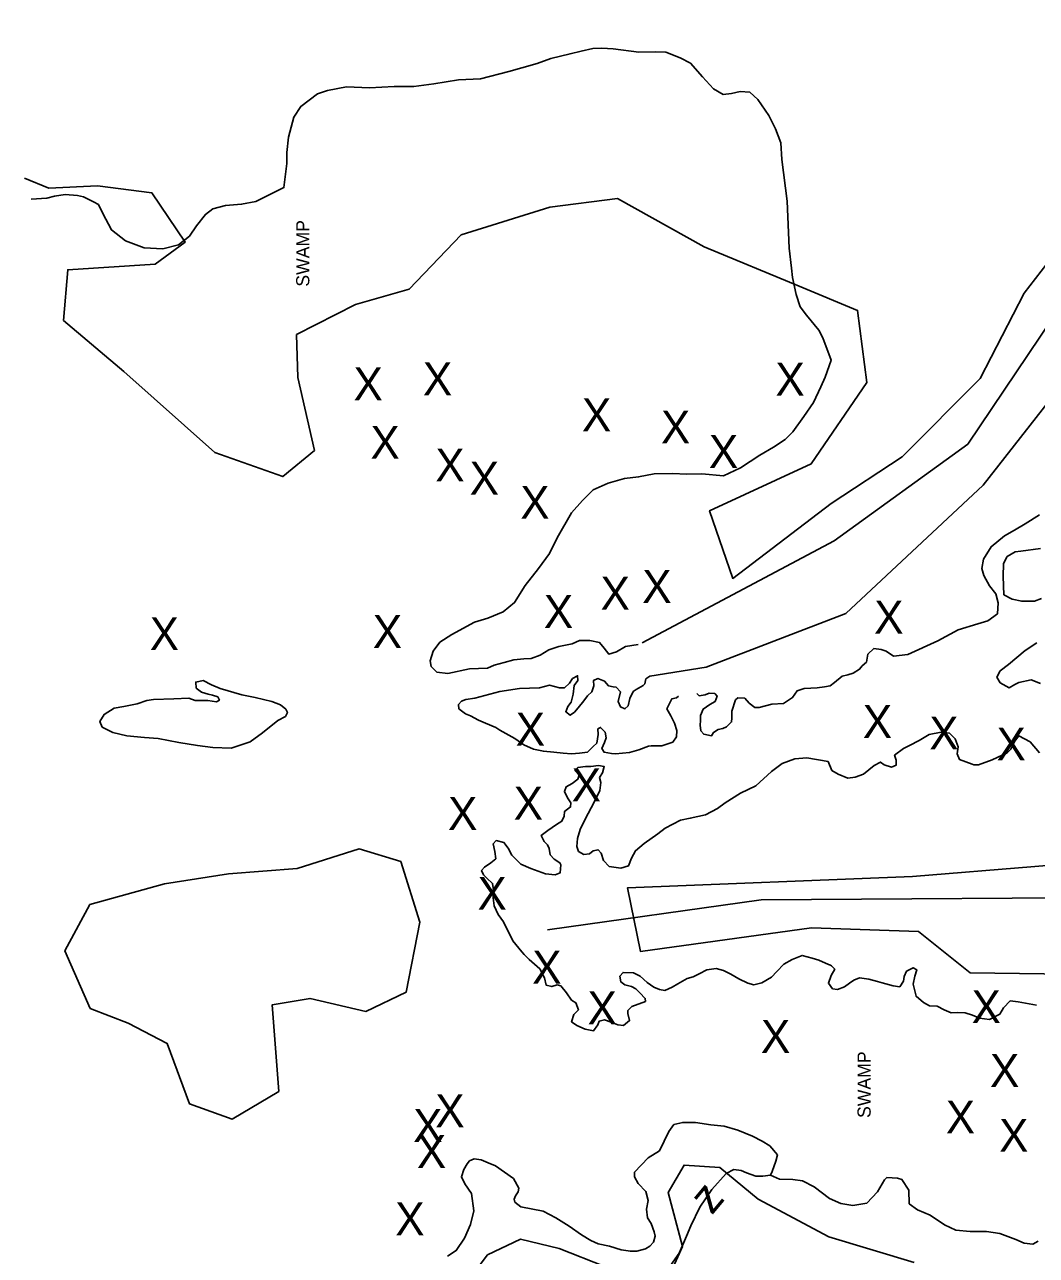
# Model space of a CAD drawing. Extents: x 2030130 to 2036320, y 723205 to 762423.
# Drawn here: x 2033457.3 to 2033764.6, y 737672 to 738045.8 of the extents above; entities that cross this region are included whole.
import ezdxf

# ---------------------------------------------------------------- set-up
doc = ezdxf.new("R2010")
doc.units = 0
for name, color, linetype in [('Draft_Station Tics Major', 7, 'Continuous'), ('Exist Terrain Model Ground Surface', 7, 'Continuous'), ('Prop Alignment Horizontal', 7, 'Continuous'), ('Prop Alignment Vertical', 7, 'Continuous')]:
    doc.layers.add(name, color=color, linetype=linetype)

msp = doc.modelspace()

# ---------------------------------------------------------------- linework, layer by layer
at = {"layer": 'Draft_Station Tics Major'}
for points in [[(2033781.5, 737990.94), (2033760.88, 737964.24), (2033747.53, 737938.3), (2033723.82, 737914.57), (2033702.29, 737900.41), (2033672.4, 737877.61), (2033665.33, 737898.19), (2033696.22, 737912.41), (2033713.11, 737937.08), (2033710.29, 737959.02), (2033692.53, 737966.39), (2033663.66, 737978.36), (2033637.36, 737993.04), (2033616.87, 737990.33), (2033589.93, 737981.95), (2033574.15, 737965.43), (2033557.84, 737960.78), (2033539.85, 737951.68), (2033540.35, 737938.62), (2033545.4, 737916.5), (2033535.74, 737908.54), (2033515.07, 737915.85), (2033487.41, 737940.44), (2033469.17, 737956), (2033470.42, 737971.39), (2033496.95, 737973.05), (2033506.06, 737979.7), (2033495.98, 737994.69), (2033479.42, 737996.89), (2033464.64, 737996.16), (2033457.33, 737999.22)], [(2033499.82, 737784.91), (2033519.26, 737787.91), (2033540.12, 737789.56), (2033558.96, 737795.48), (2033571.53, 737791.64), (2033577.32, 737773.2), (2033573.17, 737751.94), (2033560.91, 737746.14), (2033544, 737750.07), (2033532.49, 737748.08), (2033534.55, 737721.81), (2033520.39, 737713.42), (2033507.45, 737718.05), (2033500.6, 737736.39), (2033488.74, 737742.58)], [(2033781.79, 737757.38), (2033744.5, 737757.8), (2033728.83, 737770.41), (2033696.3, 737771.51), (2033644.35, 737764.35), (2033640.42, 737783.68), (2033726.95, 737787.05), (2033801.29, 737793.2)], [(2033488.74, 737742.58), (2033477.24, 737747.05), (2033469.58, 737764.48), (2033477.14, 737778.55), (2033499.82, 737784.91)], [(2033653.8, 737667.32), (2033657.1, 737674.75), (2033652.75, 737691.1), (2033657.62, 737699.45), (2033668.41, 737698.75), (2033680.11, 737689.15), (2033701.6, 737677.71), (2033727.44, 737669.82)], [(2033593.73, 737666.73), (2033597.94, 737672.21), (2033607.93, 737676.94), (2033619.62, 737674.1), (2033633.56, 737668.67)]]:
    msp.add_lwpolyline(points, dxfattribs=at)
at = {"layer": 'Exist Terrain Model Ground Surface'}
msp.add_lwpolyline([(2033964.63, 738000.66), (2033931.26, 737901.48), (2033914.62, 737851.16), (2033850.12, 737809.52), (2033803.03, 737780.8), (2033680.98, 737780.05), (2033616.14, 737770.94)], dxfattribs=at)
at = {"layer": 'Prop Alignment Horizontal'}
msp.add_line((2033647.24, 737847.97), (2033664.33, 737850.64), dxfattribs=at)
for points in [[(2033664.33, 737850.64), (2033706.74, 737866.99), (2033748.47, 737905.92), (2033780.57, 737947.09), (2033807.33, 737978.27), (2033840.77, 738020.75), (2033893, 738032.33), (2033936.05, 738045.81)], [(2033592.41, 737850.17), (2033585.83, 737848.73), (2033582.48, 737849.2), (2033580.79, 737850.89), (2033580.5, 737852.61), (2033581.36, 737855.5), (2033583.47, 737858.23), (2033587.02, 737860.6), (2033593.91, 737864.35), (2033597.96, 737865.51), (2033602.7, 737867.46), (2033606.13, 737870.29), (2033609.35, 737875.51), (2033613.36, 737880.64), (2033616.7, 737885.19), (2033619.05, 737889.96), (2033623.44, 737897.53), (2033626.76, 737901.29), (2033629.94, 737904.53), (2033634.55, 737906.6), (2033639.53, 737907.95), (2033643.77, 737908.45), (2033648.48, 737909.34), (2033654.1, 737909.48), (2033658.46, 737909.25), (2033662.96, 737909.42), (2033669.55, 737908.81), (2033674.76, 737911.21), (2033680.59, 737915.05), (2033684.8, 737917.46), (2033688.29, 737919.83), (2033690.66, 737922.16), (2033694, 737926.78), (2033696.86, 737931.01), (2033699.08, 737935.85), (2033700.4, 737938.73), (2033702.23, 737943.91), (2033699.74, 737950.64), (2033698.53, 737952.98), (2033694.74, 737957.62), (2033692.87, 737960.11), (2033691.64, 737963.9), (2033690.49, 737969.01), (2033690.22, 737971.86), (2033689.5, 737977.95), (2033688.89, 737992.24), (2033687.25, 738004.83), (2033687.03, 738009.92), (2033685.34, 738014.19), (2033683.38, 738018.2), (2033679.98, 738023.03), (2033677.52, 738025.33), (2033674.68, 738025.52), (2033672.03, 738024.92), (2033669.51, 738024.58), (2033666.51, 738026.3), (2033663.22, 738030), (2033659.54, 738034.12), (2033656.41, 738035.77), (2033652.08, 738037.45), (2033648.84, 738037.52), (2033643.82, 738037.43), (2033636.05, 738038.46), (2033632.61, 738038.67), (2033629.84, 738038.53), (2033626.38, 738037.75), (2033623, 738036.96), (2033617.15, 738035.57), (2033612.95, 738034.01), (2033608.36, 738032.66), (2033604.38, 738031.56), (2033595.74, 738029.37), (2033589.12, 738029.05), (2033581.56, 738027.83), (2033575.53, 738027.04), (2033569.52, 738027.03), (2033562.04, 738026.6), (2033555.05, 738026.89), (2033549.34, 738025.82), (2033546.28, 738024.77), (2033541.17, 738020.98), (2033539.05, 738017.66), (2033537.46, 738011.61), (2033536.97, 738007), (2033536.96, 738003.63), (2033536.07, 737996.31), (2033527.59, 737992.07), (2033523.21, 737991.24), (2033518.31, 737990.89), (2033514.52, 737989.91), (2033512.24, 737988.18), (2033509.52, 737984.74), (2033507.4, 737981.61), (2033504.04, 737978.91), (2033499.26, 737977.76), (2033493.65, 737978.01), (2033488.01, 737980.19), (2033483.72, 737983.45), (2033481.06, 737988.47), (2033479.73, 737991.14), (2033478.23, 737991.96)], [(2033821.06, 738029.09), (2033808.81, 737994.65), (2033773.1, 737961.98), (2033743.74, 737918.37), (2033703.21, 737889.06), (2033644.85, 737858.08)], [(2033478.23, 737991.96), (2033475.22, 737993.48), (2033473.38, 737993.92), (2033469.68, 737994.2), (2033466.43, 737993.68), (2033464.04, 737993.13), (2033459.28, 737992.78)], [(2033721.22, 737854.01), (2033725.52, 737854.51), (2033734.64, 737858.66), (2033740.85, 737861.96), (2033746.76, 737863.81), (2033749.88, 737864.73), (2033752.76, 737866.91), (2033752.97, 737870.2), (2033752.24, 737872.98), (2033750.31, 737875.4), (2033748.66, 737878.54), (2033748.05, 737880.66), (2033748.51, 737883.49), (2033750.9, 737887.26), (2033754.93, 737890.53), (2033757.94, 737892.31), (2033761.21, 737894.22), (2033765.49, 737896.9)], [(2033765.86, 737886.73), (2033759.84, 737885.88), (2033758.12, 737885.65), (2033755.71, 737884.25), (2033754.61, 737882.17), (2033754.46, 737878.21), (2033754.67, 737872.67), (2033757.28, 737871.36), (2033760.17, 737870.7), (2033763.99, 737870.68), (2033766.19, 737871.56)], [(2033643.66, 737857.52), (2033639.84, 737856.92), (2033637.04, 737855.33), (2033634.78, 737854.59), (2033633.3, 737856.4), (2033631.95, 737858.14), (2033629, 737858.74), (2033625.83, 737858.8), (2033623.64, 737857.8), (2033619.53, 737856.96), (2033616.54, 737855.91), (2033613.93, 737854.32), (2033611.2, 737853.26), (2033608.9, 737853.24), (2033605.85, 737852.85), (2033603, 737852.12), (2033599.95, 737851.26), (2033597.95, 737850.38), (2033592.41, 737850.17)], [(2033661.52, 737842.65), (2033662.2, 737841.98), (2033663.99, 737842.27), (2033665.25, 737842.77), (2033666.9, 737842.67), (2033667.6, 737841.86), (2033667.04, 737840.29), (2033665.37, 737839.34), (2033663.36, 737837.93), (2033662.6, 737836.04), (2033662.56, 737834.46), (2033662.47, 737833.07), (2033662.69, 737831.29), (2033663.59, 737830.28), (2033665.89, 737829.77), (2033666.51, 737830.88), (2033667.91, 737831.7), (2033669.37, 737832.07), (2033670.5, 737832.57), (2033672.05, 737834.05), (2033672.14, 737835.17), (2033672.06, 737837.35), (2033673.25, 737840.75), (2033673.92, 737841.33), (2033676.03, 737841.22), (2033677.38, 737839.74), (2033679.07, 737838.38), (2033680.39, 737838.42), (2033684.23, 737839.39), (2033687.8, 737839.64), (2033690.54, 737841.43), (2033691.91, 737843.44), (2033694.03, 737844.19), (2033696.08, 737844.34), (2033697.99, 737844.36), (2033700.24, 737844.71), (2033701.97, 737845), (2033703.31, 737846.03), (2033705.59, 737847.89), (2033707.31, 737848.32), (2033708.91, 737848.87), (2033710.91, 737850.02), (2033711.73, 737851.05), (2033713, 737852.21), (2033713.45, 737854.58), (2033715.2, 737856.32), (2033717.44, 737856.07), (2033719.01, 737855.58), (2033721.22, 737854.01)], [(2033764.77, 737858.07), (2033761.16, 737855.78), (2033758.67, 737853.59), (2033756.12, 737851.47), (2033753.57, 737849.54), (2033752.54, 737847.59), (2033753.62, 737845.92), (2033756.29, 737844.41), (2033758.09, 737845.36), (2033759.23, 737845.99), (2033763.01, 737846.83), (2033765.82, 737845.72)], [(2033594.06, 737841.3), (2033601.69, 737843.31), (2033607.64, 737844.17), (2033613.71, 737844.36), (2033616.77, 737845.22), (2033619.72, 737844.36), (2033621.3, 737844.4), (2033622.78, 737845.81), (2033623.73, 737847.18), (2033625.27, 737848.07), (2033625.3, 737846.62), (2033624.21, 737845.06), (2033623.96, 737842.43), (2033623.31, 737840.07), (2033622.3, 737838.77), (2033621.67, 737837.13), (2033623.03, 737836.05), (2033624.3, 737837.01), (2033625.45, 737838.3), (2033627.15, 737840.44), (2033628.23, 737841.94), (2033629.58, 737843.16), (2033630.15, 737844.99), (2033630.12, 737846.64), (2033631.38, 737847.21), (2033633.48, 737846.44), (2033634.63, 737845.03), (2033636.08, 737844.67), (2033637, 737844.58), (2033638.29, 737843.23), (2033637.63, 737840.21), (2033638.32, 737838.62), (2033639.62, 737837.99), (2033640.63, 737838.96), (2033641.14, 737841.19), (2033642.11, 737843.28), (2033643.05, 737843.92), (2033645.19, 737845.06), (2033645.66, 737845.64), (2033645.96, 737847.09), (2033647.24, 737847.97)], [(2033527.32, 737841.44), (2033523.25, 737842.32), (2033516.75, 737844.18), (2033514.06, 737845.3), (2033511.51, 737846.61), (2033509.32, 737846.13), (2033509.42, 737844.34), (2033511.04, 737843.05), (2033513.07, 737842.48), (2033514.39, 737842.12), (2033515.96, 737841.69), (2033516.47, 737840.69), (2033515.6, 737840.11), (2033512.97, 737840.5), (2033509.13, 737840.58), (2033507.17, 737841.29), (2033502.65, 737841.06)], [(2033502.65, 737841.06), (2033496.51, 737840.86), (2033494.46, 737840.58), (2033491.47, 737839.52), (2033487.43, 737838.69), (2033484.52, 737838.22), (2033481.51, 737836.31), (2033480.21, 737834.16), (2033480.9, 737832.5), (2033484.1, 737830.85), (2033488.36, 737829.83), (2033493.76, 737829.32), (2033497.84, 737828.96), (2033504.21, 737827.77), (2033509.79, 737826.86), (2033514.46, 737826.29), (2033520.06, 737826.1), (2033525.84, 737828.02), (2033529.53, 737830.71), (2033534.23, 737834.43), (2033536.56, 737835.7), (2033537.12, 737836.94), (2033536.61, 737837.87), (2033534.99, 737839.23), (2033532.44, 737840.27), (2033527.32, 737841.44)], [(2033594.06, 737841.3), (2033591.35, 737840.83), (2033590.02, 737840.33), (2033589.14, 737839.36), (2033589.24, 737838.04), (2033591.25, 737836.48), (2033592.69, 737835.86), (2033595.17, 737834.61), (2033597.32, 737833.64), (2033600.46, 737832.32), (2033601.63, 737831.57), (2033606.25, 737828.96), (2033608.98, 737827.06), (2033611.92, 737825.74), (2033614.88, 737825.15), (2033618.03, 737824.81), (2033620.86, 737824.56), (2033623.37, 737824.37), (2033625.88, 737824.58), (2033628.26, 737824.85), (2033629.94, 737826.53), (2033631.09, 737827.63), (2033631.54, 737830.26), (2033631.44, 737831.91), (2033632.25, 737832.35), (2033633.6, 737830.94), (2033633.89, 737829.22), (2033633.4, 737827.84), (2033632.63, 737825.95), (2033633.33, 737824.81), (2033635.57, 737824.43), (2033636.82, 737824.34), (2033640.98, 737824.77), (2033643.9, 737825.57), (2033646.83, 737826.69), (2033647.62, 737826.8), (2033650.85, 737826.8), (2033654.17, 737827.91), (2033655.27, 737829.54), (2033655.44, 737831.45), (2033654.7, 737833.64), (2033653.62, 737835.91), (2033652.35, 737837.98), (2033653.87, 737841.04), (2033655.26, 737841.34), (2033655.89, 737841.91)], [(2033765.49, 737824.62), (2033762.66, 737828.04), (2033759.27, 737829.83), (2033758.05, 737828.15), (2033756.87, 737825.73), (2033755.73, 737824.7), (2033751.2, 737822.56), (2033747.01, 737821), (2033745.56, 737820.97), (2033745.04, 737821.24), (2033741.24, 737822.58), (2033740.49, 737824.31), (2033740.86, 737826.48), (2033739.93, 737828.87), (2033738.19, 737830.62), (2033735.69, 737830.94), (2033732.04, 737830.23), (2033729.04, 737828.45), (2033726.1, 737826.87), (2033724.23, 737825.98), (2033721.55, 737823.93), (2033722.05, 737822.41), (2033722.01, 737820.95), (2033720.55, 737820.33), (2033718.39, 737821.03), (2033717.22, 737821.85), (2033715.35, 737820.77), (2033712.06, 737818.14), (2033709.6, 737817.27), (2033707.29, 737816.99), (2033704.35, 737818.18), (2033702.52, 737819.34), (2033701.33, 737822.07)], [(2033701.33, 737822.07), (2033694.89, 737823.13), (2033691.26, 737822.82), (2033687.4, 737821.38), (2033684.18, 737818.95), (2033679.34, 737814.64), (2033674.74, 737812.43), (2033670.06, 737809.43), (2033667.71, 737807.7), (2033664.11, 737805.8), (2033659.47, 737804.78), (2033656.49, 737804.19), (2033651.89, 737801.78), (2033649.67, 737800.05), (2033645.52, 737797.17), (2033642.83, 737794.93), (2033641.67, 737792.71), (2033640.76, 737790.35), (2033638.37, 737789.62), (2033634.88, 737790.09), (2033633.14, 737791.97), (2033632.46, 737794.16), (2033631.5, 737795.24), (2033629.98, 737794.94), (2033628.83, 737793.98), (2033627.11, 737793.75), (2033625.55, 737794.71), (2033625.06, 737796.24), (2033625.24, 737798.61), (2033626.09, 737801.42), (2033627.55, 737804.56), (2033630.3, 737809.71), (2033632.02, 737813.23), (2033632.27, 737815.6), (2033631.91, 737817.19), (2033632.8, 737818.56), (2033633.37, 737820.46), (2033631.6, 737820.82), (2033629.28, 737820.48), (2033627.63, 737820.52), (2033625.38, 737820.17), (2033624.44, 737819.33), (2033625.73, 737817.92), (2033625.31, 737816.61), (2033623.63, 737815.33), (2033621.83, 737814.38), (2033621.27, 737812.94), (2033622.15, 737811.01), (2033623.24, 737809.47), (2033623.14, 737808.22), (2033621.33, 737806.87), (2033621.17, 737805.42), (2033620.48, 737803.86), (2033618.87, 737802.84), (2033616.26, 737801.11), (2033614.18, 737799.51), (2033615.13, 737797.71), (2033616.1, 737796.76), (2033616.6, 737795.57), (2033616.96, 737793.71), (2033618.11, 737792.37), (2033619.87, 737791.27), (2033620.19, 737790.67), (2033619.94, 737788.17), (2033618.47, 737787.61), (2033615.51, 737787.87), (2033611.06, 737789.49), (2033607.99, 737790.87), (2033605.28, 737793.57), (2033604.14, 737795.71), (2033602.86, 737797.45), (2033600.5, 737798.03), (2033599.62, 737796.99), (2033600.1, 737794.67), (2033600.38, 737792.49), (2033598.96, 737791.2), (2033596.96, 737789.93), (2033596.08, 737788.89), (2033596.64, 737787.63), (2033597.68, 737786.62), (2033599.42, 737784.99), (2033599.71, 737783.01), (2033599.66, 737780.64), (2033599.93, 737778.19), (2033601.13, 737775.53), (2033602.73, 737773.32), (2033605.57, 737767.58), (2033608.33, 737764.22)], [(2033608.33, 737764.22), (2033609.04, 737763.42), (2033610.52, 737761.87), (2033613.76, 737759.03), (2033615.21, 737756.29), (2033615.69, 737754.1), (2033617.4, 737753.67), (2033619.06, 737754.23), (2033620.17, 737753.87), (2033621.91, 737751.79), (2033623.38, 737749.58), (2033624.68, 737748.76), (2033625.49, 737746.64), (2033624.07, 737745.15), (2033623.43, 737742.99), (2033624.99, 737741.83), (2033627.6, 737740.72), (2033630.1, 737740.27), (2033631.39, 737742.09), (2033631.81, 737743.13), (2033633.4, 737743.56), (2033635.5, 737742.86), (2033637.52, 737742.02), (2033639.23, 737741.85), (2033641.05, 737743.33), (2033640.5, 737745.52), (2033640.52, 737746.37), (2033641.73, 737747.6), (2033645.86, 737749.16), (2033645.81, 737750.08), (2033644.2, 737751.77), (2033642.91, 737752.98), (2033641.67, 737753.67), (2033639.57, 737754.24), (2033638.4, 737755.06), (2033638.11, 737756.78), (2033639.06, 737757.95), (2033642.22, 737757.88), (2033644.31, 737756.78), (2033646.38, 737754.95), (2033648.46, 737753.52), (2033650.15, 737752.76), (2033651.8, 737752.52), (2033654, 737753.53), (2033655.67, 737754.48), (2033658.54, 737756.13), (2033660.33, 737756.62), (2033662.2, 737757.5), (2033664.46, 737758.71), (2033667.38, 737759.17), (2033669.54, 737758.53), (2033671.82, 737757.43), (2033674.23, 737755.99), (2033676.97, 737754.68), (2033678.81, 737754.24), (2033681.26, 737754.84), (2033684.14, 737756.56), (2033685.75, 737758.24), (2033687.85, 737760.44), (2033690.39, 737761.9), (2033693.45, 737763.15), (2033696.53, 737762.29), (2033698.56, 737761.65), (2033701.5, 737760.4), (2033702.09, 737760.19), (2033702.41, 737759.99), (2033703.38, 737758.98), (2033702.28, 737757.02), (2033701.44, 737754.67), (2033702.72, 737752.99), (2033704.23, 737752.76), (2033706.36, 737753.64), (2033707.84, 737754.72), (2033709.17, 737755.62), (2033710.84, 737756.31), (2033713.73, 737755.91), (2033716.35, 737755.26), (2033717.73, 737754.77), (2033721.07, 737753.91), (2033723.11, 737753.6), (2033724.27, 737755.35), (2033724.43, 737756.74), (2033725.13, 737758.3), (2033727.13, 737759.38), (2033728.24, 737758.76), (2033727.67, 737756.86), (2033727.15, 737754.37), (2033728.06, 737750.72), (2033730.26, 737748.83), (2033732.09, 737747.86), (2033734.46, 737747.68), (2033736.61, 737746.58), (2033738.7, 737745.74), (2033740.68, 737745.76), (2033742.92, 737745.71), (2033745.21, 737744.94), (2033747.3, 737744.03), (2033750.33, 737743.7), (2033753.46, 737745.28), (2033754.63, 737747.24), (2033756.59, 737749.37)], [(2033756.59, 737749.37), (2033759.02, 737749.05), (2033764.67, 737748.01)], [(2033765.17, 737676.37), (2033763.51, 737675.44), (2033760.9, 737675.77), (2033758.31, 737676.9), (2033753.44, 737678.68), (2033749.46, 737679.32), (2033744.48, 737679.33), (2033740.16, 737679.65), (2033736.67, 737681.33), (2033732.36, 737684.2), (2033728.47, 737685.89), (2033725.97, 737687.73), (2033725.83, 737691.8), (2033723.76, 737695.07), (2033722.39, 737695.51), (2033719.19, 737695.73), (2033718.51, 737694.96), (2033716.37, 737691.35), (2033713.06, 737687.84), (2033708.84, 737687.18), (2033705.19, 737687.74), (2033701.76, 737689.28), (2033697.14, 737692.83), (2033693.59, 737694.63), (2033690.58, 737695.05), (2033686.59, 737695.16), (2033683.87, 737696.42), (2033684.3, 737697.53), (2033685.5, 737700.64), (2033686.02, 737702.59), (2033683.6, 737705.28), (2033681.28, 737706.73), (2033678.38, 737708.19), (2033673.91, 737710.09), (2033669.81, 737711.25), (2033665.76, 737711.7), (2033661.06, 737712.36), (2033657.19, 737712.4), (2033654.49, 737711.83), (2033652.92, 737709.64), (2033650.13, 737703.82), (2033646.72, 737701.69), (2033642.59, 737697.29), (2033642.55, 737695.91), (2033643.61, 737693.85), (2033645.96, 737691.42), (2033646.67, 737688.71), (2033646.14, 737686.11), (2033646.52, 737683.41), (2033647.59, 737681.74), (2033648.56, 737679.22), (2033648.79, 737677.9), (2033648.34, 737676.01), (2033647.19, 737674.8), (2033645.86, 737674.05), (2033643.28, 737673.27), (2033641.31, 737673.27), (2033638.5, 737673.74), (2033634.93, 737674.83), (2033631.54, 737675.58), (2033629.28, 737676.56), (2033626.44, 737678.28), (2033622.71, 737680.88), (2033618.66, 737683.43), (2033614.78, 737685.44), (2033608.07, 737686.75), (2033606.21, 737688.24), (2033605.97, 737689.1), (2033606.4, 737690.14), (2033607.22, 737691.3), (2033607.45, 737692.47), (2033605.76, 737695.4), (2033600.36, 737699.23), (2033598.1, 737700.15), (2033596.02, 737701), (2033593.8, 737701.32), (2033592.48, 737700.77), (2033591.73, 737699.81), (2033590.76, 737698.13), (2033589.97, 737695.86), (2033591.03, 737693.8), (2033593.04, 737690.79), (2033593.74, 737685.52)], [(2033652.77, 737667.92), (2033656.14, 737672.7), (2033658.33, 737677.84), (2033659.61, 737680.96), (2033662.34, 737686.68), (2033666.05, 737692.04), (2033670.41, 737696.92), (2033672.68, 737698.1), (2033674.91, 737697.84), (2033676.6, 737697.13), (2033679.34, 737696.13), (2033681.51, 737696.07), (2033683.87, 737696.42)], [(2033593.74, 737685.52), (2033592.77, 737681.42), (2033590.94, 737677.21), (2033588.41, 737673.48), (2033585.8, 737671.79)]]:
    msp.add_lwpolyline(points, dxfattribs=at)

# ---------------------------------------------------------------- texts
at = {"layer": 'Draft_Station Tics Major'}
for p in [(2033557.2, 737931.7), (2033578.28, 737933.21), (2033685.33, 737933.1), (2033626.57, 737922.29), (2033650.56, 737918.6), (2033562.34, 737913.96), (2033665.12, 737911.18), (2033582.05, 737907.08), (2033592.48, 737903.04), (2033607.84, 737895.73), (2033632.22, 737868.11), (2033644.89, 737870.2), (2033615, 737862.57), (2033715.32, 737860.89), (2033563.05, 737856.47), (2033495.3, 737855.85), (2033606.46, 737826.85), (2033711.86, 737829.14), (2033732.04, 737825.68), (2033752.48, 737822.33), (2033623.45, 737809.9), (2033605.84, 737804.37), (2033585.91, 737801.26), (2033594.85, 737776.99), (2033611.47, 737754.58), (2033628.28, 737742.2), (2033744.89, 737742.56), (2033680.93, 737733.54), (2033750.49, 737723.19), (2033582.03, 737710.95), (2033737.07, 737709.05), (2033575.33, 737706.51), (2033753.26, 737703.48), (2033576.45, 737698.57), (2033569.88, 737678.1)]:
    msp.add_text('X', height=10, dxfattribs=at).set_placement(p)
at = {"layer": 'Prop Alignment Horizontal'}
msp.add_text('z', height=10, rotation=50.1614, dxfattribs=at).set_placement((2033666.02, 737684.04))
at = {"layer": 'Prop Alignment Vertical'}
for p in [(2033543.8, 737966.23), (2033714.27, 737713.77)]:
    msp.add_text('SWAMP', height=4, rotation=90, dxfattribs=at).set_placement(p)

doc.saveas('drawing.dxf')
